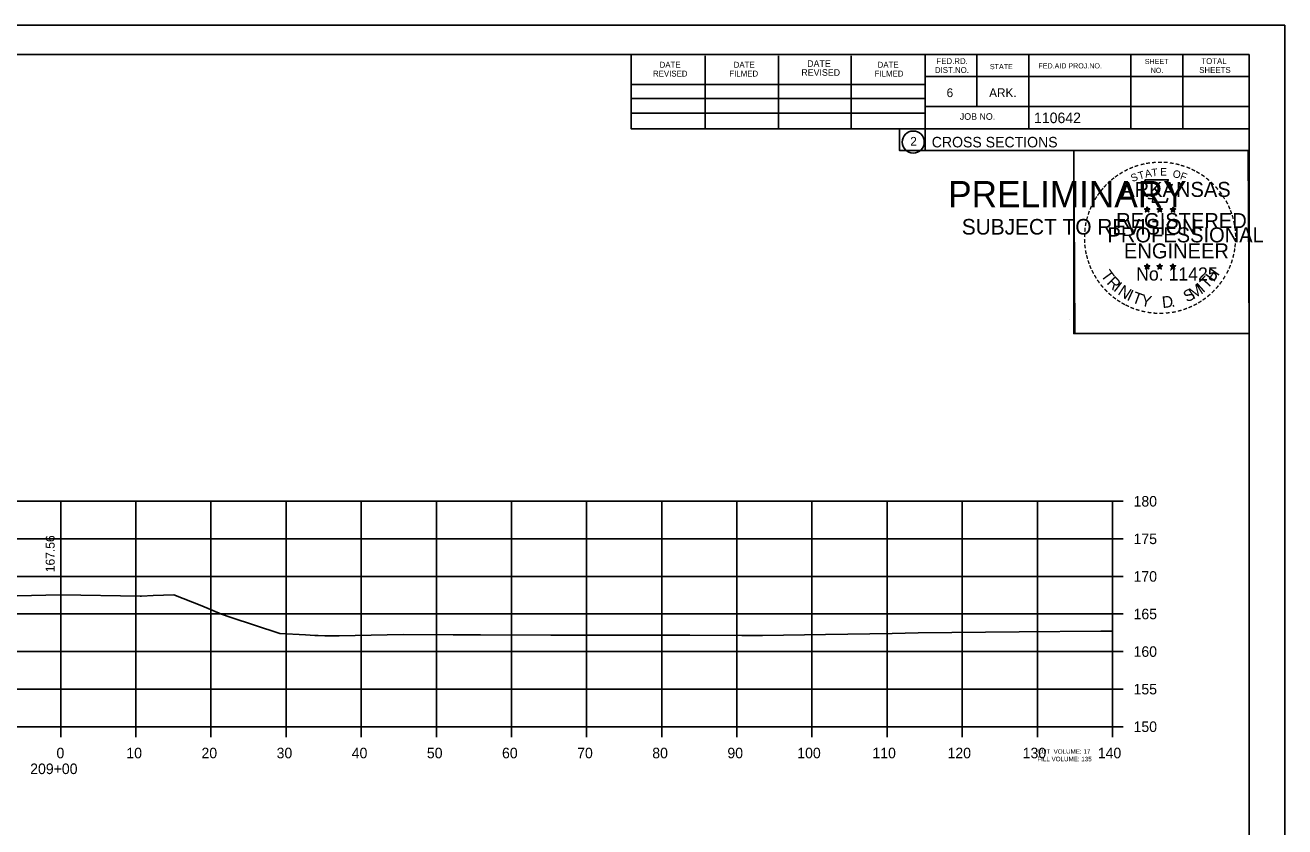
# Model space of a CAD drawing. Extents: x 1368503 to 1373085, y 379840 to 381833.
# Drawn here: x 1368668.3 to 1368836, y 380446.1 to 380552.7 of the extents above; entities that cross this region are included whole.
import ezdxf

# ---------------------------------------------------------------- set-up
doc = ezdxf.new("R2010")
doc.units = 0
for name, color, linetype in [('S_BRIDGE', 7, 'Continuous'), ('S_EDGE_PAVEMENT', 7, 'Continuous'), ('S_LANDSCAPING', 7, 'Continuous'), ('S_MISC_BOUNDARY', 7, 'Continuous'), ('S_MISC_BOUNDARY_ANNOT', 7, 'Continuous'), ('S_PHOTO_CENTERS', 7, 'Continuous'), ('S_PHOTO_NOTES', 7, 'Continuous'), ('S_TRAILS', 7, 'Continuous'), ('S_TRAILS_ANNOT', 7, 'Continuous')]:
    doc.layers.add(name, color=color, linetype=linetype)

msp = doc.modelspace()

# ---------------------------------------------------------------- linework, layer by layer
at = {"layer": 'S_BRIDGE'}
for p, q in [((1368515.06, 380548.83), (1368831.24, 380548.83)), ((1368748.98, 380538.95), (1368748.98, 380548.83)), ((1368758.84, 380538.95), (1368758.84, 380548.63)), ((1368768.6, 380538.95), (1368768.6, 380548.63)), ((1368778.28, 380538.95), (1368778.28, 380548.63)), ((1368788.14, 380548.83), (1368788.14, 380536.03)), ((1368794.98, 380548.83), (1368794.98, 380541.89)), ((1368801.92, 380548.83), (1368801.92, 380538.95)), ((1368815.5, 380548.83), (1368815.5, 380538.95)), ((1368822.44, 380548.83), (1368822.44, 380538.95)), ((1368831.24, 380343.37), (1368831.24, 380548.83)), ((1368831.24, 380545.89), (1368788.14, 380545.89)), ((1368831.24, 380545.91), (1368831.24, 380545.91)), ((1368748.98, 380544.81), (1368788.14, 380544.81)), ((1368748.98, 380542.95), (1368788.14, 380542.95)), ((1368748.98, 380538.95), (1368748.98, 380541.01)), ((1368748.98, 380541.01), (1368788.14, 380541.01)), ((1368831.24, 380541.89), (1368788.14, 380541.89)), ((1368791.1, 380541.89), (1368831.24, 380541.89)), ((1368831.24, 380538.95), (1368748.98, 380538.95)), ((1368788.14, 380536.03), (1368831.24, 380536.03))]:
    msp.add_line(p, q, dxfattribs=at)
msp.add_circle((1368786.53, 380537.16), 1.47, dxfattribs=at)
at = {"layer": 'S_EDGE_PAVEMENT'}
for p, q in [((1368813.06, 380459.37), (1368813.06, 380489.37)), ((1368814.46, 380489.37), (1368813.06, 380489.37)), ((1368814.46, 380484.37), (1368813.06, 380484.37)), ((1368814.46, 380479.37), (1368813.06, 380479.37)), ((1368814.46, 380474.37), (1368813.06, 380474.37)), ((1368814.46, 380469.37), (1368813.06, 380469.37)), ((1368814.46, 380464.37), (1368813.06, 380464.37)), ((1368533.06, 380459.37), (1368813.06, 380459.37)), ((1368673.06, 380457.97), (1368673.06, 380459.37)), ((1368683.06, 380457.97), (1368683.06, 380459.37)), ((1368693.06, 380457.97), (1368693.06, 380459.37)), ((1368703.06, 380457.97), (1368703.06, 380459.37)), ((1368713.06, 380457.97), (1368713.06, 380459.37)), ((1368723.06, 380457.97), (1368723.06, 380459.37)), ((1368733.06, 380457.97), (1368733.06, 380459.37)), ((1368743.06, 380457.97), (1368743.06, 380459.37)), ((1368753.06, 380457.97), (1368753.06, 380459.37)), ((1368763.06, 380457.97), (1368763.06, 380459.37)), ((1368773.06, 380457.97), (1368773.06, 380459.37)), ((1368783.06, 380457.97), (1368783.06, 380459.37)), ((1368793.06, 380457.97), (1368793.06, 380459.37)), ((1368803.06, 380457.97), (1368803.06, 380459.37)), ((1368813.06, 380457.97), (1368813.06, 380459.37)), ((1368814.46, 380459.37), (1368813.06, 380459.37))]:
    msp.add_line(p, q, dxfattribs=at)
at = {"layer": 'S_LANDSCAPING'}
for p, q in [((1368817.32, 380528.28), (1368817.67, 380528.17)), ((1368817.32, 380528.28), (1368817.58, 380528.24)), ((1368817.32, 380528.28), (1368817.56, 380528.16)), ((1368817.46, 380527.87), (1368817.67, 380528.17)), ((1368817.46, 380527.87), (1368817.58, 380528.12)), ((1368817.46, 380527.87), (1368817.67, 380528.09)), ((1368817.67, 380528.54), (1368817.63, 380528.28)), ((1368817.67, 380528.17), (1368817.67, 380528.54)), ((1368817.67, 380528.54), (1368817.72, 380528.29)), ((1368818.02, 380528.28), (1368817.67, 380528.17)), ((1368817.89, 380527.87), (1368817.67, 380528.17)), ((1368817.89, 380527.87), (1368817.67, 380528.09)), ((1368818.02, 380528.28), (1368817.73, 380528.23)), ((1368817.89, 380527.87), (1368817.75, 380528.16)), ((1368818.02, 380528.28), (1368817.82, 380528.18)), ((1368818.99, 380528.28), (1368819.34, 380528.17)), ((1368818.99, 380528.28), (1368819.25, 380528.24)), ((1368818.99, 380528.28), (1368819.23, 380528.16)), ((1368819.13, 380527.87), (1368819.34, 380528.17)), ((1368819.13, 380527.87), (1368819.25, 380528.12)), ((1368819.13, 380527.87), (1368819.34, 380528.09)), ((1368819.34, 380528.54), (1368819.3, 380528.28)), ((1368819.34, 380528.17), (1368819.34, 380528.54)), ((1368819.34, 380528.54), (1368819.39, 380528.29)), ((1368819.69, 380528.28), (1368819.34, 380528.17)), ((1368819.56, 380527.87), (1368819.34, 380528.17)), ((1368819.56, 380527.87), (1368819.34, 380528.09)), ((1368819.69, 380528.28), (1368819.4, 380528.23)), ((1368819.56, 380527.87), (1368819.42, 380528.16)), ((1368819.69, 380528.28), (1368819.49, 380528.18)), ((1368820.76, 380528.27), (1368821.11, 380528.16)), ((1368820.76, 380528.27), (1368821.01, 380528.22)), ((1368820.76, 380528.27), (1368820.99, 380528.15)), ((1368820.89, 380527.86), (1368821.11, 380528.16)), ((1368820.89, 380527.86), (1368821.02, 380528.11)), ((1368820.89, 380527.86), (1368821.1, 380528.08)), ((1368821.11, 380528.52), (1368821.07, 380528.27)), ((1368821.32, 380527.86), (1368821.1, 380528.08)), ((1368821.11, 380528.16), (1368821.11, 380528.52)), ((1368821.11, 380528.52), (1368821.16, 380528.27)), ((1368821.45, 380528.27), (1368821.11, 380528.16)), ((1368821.32, 380527.86), (1368821.11, 380528.16)), ((1368821.45, 380528.27), (1368821.17, 380528.22)), ((1368821.32, 380527.86), (1368821.18, 380528.15)), ((1368821.45, 380528.27), (1368821.25, 380528.17)), ((1368817.32, 380520.71), (1368817.67, 380520.6)), ((1368817.32, 380520.71), (1368817.57, 380520.66)), ((1368817.32, 380520.71), (1368817.56, 380520.59)), ((1368817.67, 380520.96), (1368817.63, 380520.71)), ((1368817.67, 380520.6), (1368817.67, 380520.96)), ((1368817.67, 380520.96), (1368817.72, 380520.71)), ((1368818.02, 380520.71), (1368817.67, 380520.6)), ((1368818.02, 380520.71), (1368817.73, 380520.66)), ((1368818.02, 380520.71), (1368817.81, 380520.61)), ((1368818.99, 380520.71), (1368819.34, 380520.6)), ((1368818.99, 380520.71), (1368819.24, 380520.66)), ((1368818.99, 380520.71), (1368819.23, 380520.59)), ((1368819.34, 380520.96), (1368819.3, 380520.71)), ((1368819.34, 380520.6), (1368819.34, 380520.96)), ((1368819.34, 380520.96), (1368819.39, 380520.71)), ((1368819.68, 380520.71), (1368819.34, 380520.6)), ((1368819.68, 380520.71), (1368819.4, 380520.66)), ((1368819.68, 380520.71), (1368819.48, 380520.61)), ((1368820.76, 380520.7), (1368821.1, 380520.59)), ((1368820.76, 380520.7), (1368821.01, 380520.65)), ((1368820.76, 380520.7), (1368820.99, 380520.58)), ((1368821.1, 380520.95), (1368821.06, 380520.7)), ((1368821.1, 380520.59), (1368821.1, 380520.95)), ((1368821.1, 380520.95), (1368821.15, 380520.7)), ((1368821.45, 380520.7), (1368821.1, 380520.59)), ((1368821.45, 380520.7), (1368821.17, 380520.65)), ((1368821.45, 380520.7), (1368821.25, 380520.6)), ((1368817.45, 380520.3), (1368817.67, 380520.6)), ((1368817.45, 380520.3), (1368817.58, 380520.54)), ((1368817.45, 380520.3), (1368817.67, 380520.52)), ((1368817.88, 380520.3), (1368817.67, 380520.6)), ((1368817.88, 380520.3), (1368817.67, 380520.51)), ((1368817.88, 380520.3), (1368817.74, 380520.59)), ((1368819.12, 380520.3), (1368819.34, 380520.6)), ((1368819.12, 380520.3), (1368819.25, 380520.54)), ((1368819.12, 380520.3), (1368819.34, 380520.52)), ((1368819.55, 380520.3), (1368819.34, 380520.6)), ((1368819.55, 380520.3), (1368819.34, 380520.51)), ((1368819.55, 380520.3), (1368819.41, 380520.59)), ((1368820.89, 380520.29), (1368821.1, 380520.59)), ((1368820.89, 380520.29), (1368821.01, 380520.53)), ((1368820.89, 380520.29), (1368821.1, 380520.51)), ((1368821.32, 380520.29), (1368821.1, 380520.59)), ((1368821.32, 380520.29), (1368821.1, 380520.5)), ((1368821.32, 380520.29), (1368821.18, 380520.58))]:
    msp.add_line(p, q, dxfattribs=at)
for points in [[(1368817.36, 380532.16), (1368817.63, 380531.33)], [(1368820.88, 380531.24), (1368821.02, 380531.52), (1368820.33, 380531.5), (1368820.48, 380532.16), (1368817.36, 380532.16)], [(1368817.86, 380529.74), (1368817.86, 380529.65), (1368818.42, 380529.63), (1368818.37, 380529.16), (1368820.24, 380529.16), (1368820.44, 380529.69)], [(1368817.67, 380528.54), (1368817.89, 380527.87), (1368817.32, 380528.28), (1368818.02, 380528.28), (1368817.46, 380527.87), (1368817.67, 380528.54)], [(1368819.34, 380528.54), (1368819.56, 380527.87), (1368818.99, 380528.28), (1368819.69, 380528.28), (1368819.13, 380527.87), (1368819.34, 380528.54)], [(1368821.11, 380528.52), (1368821.32, 380527.86), (1368820.76, 380528.27), (1368821.45, 380528.27), (1368820.89, 380527.86), (1368821.11, 380528.52)], [(1368817.67, 380520.96), (1368817.88, 380520.3), (1368817.32, 380520.71), (1368818.02, 380520.71), (1368817.45, 380520.3), (1368817.67, 380520.96)], [(1368819.34, 380520.96), (1368819.55, 380520.3), (1368818.99, 380520.71), (1368819.68, 380520.71), (1368819.12, 380520.3), (1368819.34, 380520.96)], [(1368821.1, 380520.95), (1368821.32, 380520.29), (1368820.76, 380520.7), (1368821.45, 380520.7), (1368820.89, 380520.29), (1368821.1, 380520.95)]]:
    msp.add_lwpolyline(points, dxfattribs=at)
for centre, radius in [((1368817.67, 380528.17), 0.172), ((1368817.67, 380528.17), 0.145), ((1368817.67, 380528.17), 0.116), ((1368817.67, 380528.17), 0.0991), ((1368817.67, 380528.17), 0.0747), ((1368817.67, 380528.17), 0.0495), ((1368817.67, 380528.17), 0.0296), ((1368819.34, 380528.17), 0.172), ((1368819.34, 380528.17), 0.145), ((1368819.34, 380528.17), 0.116), ((1368819.34, 380528.17), 0.0991), ((1368819.34, 380528.17), 0.0747), ((1368819.34, 380528.17), 0.0495), ((1368819.34, 380528.17), 0.0296), ((1368821.11, 380528.16), 0.172), ((1368821.11, 380528.16), 0.145), ((1368821.11, 380528.16), 0.116), ((1368821.11, 380528.16), 0.0991), ((1368821.11, 380528.16), 0.0747), ((1368821.11, 380528.16), 0.0495), ((1368821.11, 380528.16), 0.0296), ((1368817.67, 380520.6), 0.172), ((1368817.67, 380520.6), 0.145), ((1368817.67, 380520.6), 0.116), ((1368817.67, 380520.6), 0.0991), ((1368819.34, 380520.6), 0.172), ((1368819.34, 380520.6), 0.145), ((1368819.34, 380520.6), 0.116), ((1368819.34, 380520.6), 0.0991), ((1368821.1, 380520.59), 0.172), ((1368821.1, 380520.59), 0.145), ((1368821.1, 380520.59), 0.116), ((1368817.67, 380520.6), 0.0747), ((1368817.67, 380520.6), 0.0495), ((1368817.67, 380520.6), 0.0296), ((1368819.34, 380520.6), 0.0747), ((1368819.34, 380520.6), 0.0495), ((1368819.34, 380520.6), 0.0296), ((1368821.1, 380520.59), 0.0991), ((1368821.1, 380520.59), 0.0747), ((1368821.1, 380520.59), 0.0495), ((1368821.1, 380520.59), 0.0296)]:
    msp.add_circle(centre, radius, dxfattribs=at)
at = {"layer": 'S_MISC_BOUNDARY'}
msp.add_lwpolyline([(1368663.39, 380476.72), (1368673, 380476.93), (1368673.07, 380476.93), (1368673.14, 380476.93), (1368683.64, 380476.73), (1368683.8, 380476.73), (1368685.36, 380476.81), (1368688.14, 380476.94), (1368691.83, 380475.44), (1368694.46, 380474.36), (1368695.63, 380473.97), (1368702.24, 380471.79), (1368705.64, 380471.59), (1368706.88, 380471.52), (1368707.31, 380471.5), (1368708.2, 380471.46), (1368710.12, 380471.48), (1368718.64, 380471.64), (1368725.31, 380471.59), (1368728.94, 380471.58), (1368738.31, 380471.57), (1368756.79, 380471.55), (1368763.73, 380471.52), (1368766.47, 380471.5), (1368774.85, 380471.65), (1368783.71, 380471.79), (1368787.18, 380471.85), (1368800.62, 380471.98), (1368811.49, 380472.08), (1368813.06, 380472.1)], dxfattribs=at)
at = {"layer": 'S_PHOTO_CENTERS'}
for p, q in [((1368533.06, 380489.37), (1368813.06, 380489.37)), ((1368673.06, 380459.37), (1368673.06, 380489.37)), ((1368683.06, 380459.37), (1368683.06, 380489.37)), ((1368693.06, 380459.37), (1368693.06, 380489.37)), ((1368703.06, 380459.37), (1368703.06, 380489.37)), ((1368713.06, 380459.37), (1368713.06, 380489.37)), ((1368723.06, 380459.37), (1368723.06, 380489.37)), ((1368733.06, 380459.37), (1368733.06, 380489.37)), ((1368743.06, 380459.37), (1368743.06, 380489.37)), ((1368753.06, 380459.37), (1368753.06, 380489.37)), ((1368763.06, 380459.37), (1368763.06, 380489.37)), ((1368773.06, 380459.37), (1368773.06, 380489.37)), ((1368783.06, 380459.37), (1368783.06, 380489.37)), ((1368793.06, 380459.37), (1368793.06, 380489.37)), ((1368803.06, 380459.37), (1368803.06, 380489.37)), ((1368813.06, 380459.37), (1368813.06, 380489.37)), ((1368533.06, 380484.37), (1368813.06, 380484.37)), ((1368533.06, 380479.37), (1368813.06, 380479.37)), ((1368533.06, 380474.37), (1368813.06, 380474.37)), ((1368533.06, 380469.37), (1368813.06, 380469.37)), ((1368533.06, 380464.37), (1368813.06, 380464.37)), ((1368533.06, 380459.37), (1368813.06, 380459.37))]:
    msp.add_line(p, q, dxfattribs=at)
at = {"layer": 'S_PHOTO_NOTES'}
for p, q in [((1368502.66, 380552.72), (1368835.99, 380552.72)), ((1368807.27, 380513.57), (1368807.27, 380513.57))]:
    msp.add_line(p, q, dxfattribs=at)
for points in [[(1368502.65, 380552.72), (1368835.99, 380552.72), (1368835.99, 380339.38), (1368502.65, 380339.38)], [(1368748.98, 380548.83), (1368748.98, 380538.95), (1368784.71, 380538.95), (1368784.71, 380536.03), (1368807.91, 380536.03), (1368807.91, 380511.69), (1368831.24, 380511.69), (1368831.24, 380343.37), (1368515.06, 380343.37), (1368515.06, 380548.83)], [(1368807.91, 380536.03), (1368831.12, 380536.03), (1368831.24, 380511.69), (1368808.03, 380511.69)]]:
    msp.add_lwpolyline(points, close=True, dxfattribs=at)

# ---------------------------------------------------------------- texts
at = {"layer": 'S_BRIDGE'}
for s, height, p in [('DATE', 0.782, (1368752.78, 380547.07)), ('DATE', 0.782, (1368762.64, 380547.07)), ('DATE', 0.879, (1368772.42, 380547.17)), ('DATE', 0.782, (1368781.8, 380547.07)), ('FED.RD.', 0.782, (1368789.62, 380547.55)), ('STATE', 0.684, (1368796.74, 380546.87)), ('FED.AID PROJ.NO.', 0.684, (1368803.2, 380546.97)), ('SHEET', 0.684, (1368817.36, 380547.55)), ('TOTAL', 0.782, (1368824.88, 380547.55)), ('REVISED', 0.782, (1368751.9, 380545.89)), ('FILMED', 0.782, (1368762.06, 380545.89)), ('REVISED', 0.879, (1368771.64, 380545.99)), ('FILMED', 0.782, (1368781.4, 380545.89)), ('DIST.NO.', 0.782, (1368789.42, 380546.37)), ('NO.', 0.684, (1368818.14, 380546.37)), ('SHEETS', 0.782, (1368824.6, 380546.37)), ('6', 1.17, (1368790.98, 380543.15)), ('ARK.', 1.172, (1368796.64, 380543.15)), ('JOB NO.', 0.879, (1368792.74, 380540.13)), ('110642', 1.4, (1368802.61, 380539.69)), ('2', 1.17, (1368786.14, 380536.68)), ('CROSS SECTIONS', 1.4, (1368789, 380536.46))]:
    msp.add_text(s, height=height, rotation=360, dxfattribs=at).set_placement(p)
at = {"layer": 'S_LANDSCAPING'}
for s, height, rotation, p in [('-', 1.6, 19.1761, (1368816.11, 380533.29)), ('-', 1.6, 13.6301, (1368816.86, 380533.53)), ('-', 1.6, 10.2193, (1368817.54, 380533.69)), ('-', 1.6, 5.8968, (1368818.27, 380533.8)), ('-', 1.6, 0.1862, (1368819.04, 380533.87)), ('-', 1.6, 357.743, (1368819.76, 380533.86)), ('-', 1.6, 352.1617, (1368820.51, 380533.8)), ('-', 1.6, 347.2049, (1368821.23, 380533.69)), ('-', 1.6, 342.3362, (1368821.86, 380533.53)), ('-', 1.6, 38.9507, (1368813.19, 380531.56)), ('-', 1.6, 36.2317, (1368813.67, 380531.94)), ('-', 1.6, 34.0636, (1368814.25, 380532.33)), ('-', 1.6, 28.7918, (1368814.85, 380532.7)), ('-', 1.6, 24.3072, (1368815.48, 380533.02)), ('S', 1, 21.594, (1368815.72, 380531.84)), ('T', 1, 16.4036, (1368816.63, 380532.17)), ('A', 1, 11.2132, (1368817.46, 380532.42)), ('T', 1, 6.0228, (1368818.31, 380532.59)), ('E', 1, 0.8323, (1368819.41, 380532.7)), ('O', 1, 350.4515, (1368821.02, 380532.49)), ('F', 1, 340.0707, (1368821.97, 380532.26)), ('-', 1.6, 337.8551, (1368822.6, 380533.31)), ('-', 1.6, 334.1211, (1368823.23, 380533.04)), ('-', 1.6, 329.6409, (1368823.81, 380532.76)), ('-', 1.6, 325.8627, (1368824.45, 380532.4)), ('-', 1.6, 320.5297, (1368825.06, 380531.97)), ('-', 1.6, 50.6142, (1368811.91, 380530.18)), ('-', 1.6, 48.423, (1368812.31, 380530.66)), ('-', 1.6, 42.9622, (1368812.76, 380531.14)), ('ARKANSAS', 2, 360, (1368814.22, 380529.87)), ('-', 1.6, 315.5786, (1368825.66, 380531.48)), ('-', 1.6, 309.8797, (1368826.23, 380530.93)), ('-', 1.6, 62.8713, (1368810.86, 380528.47)), ('-', 1.6, 58.0706, (1368811.17, 380529.08)), ('-', 1.6, 54.2325, (1368811.5, 380529.61)), ('-', 1.6, 306.6522, (1368826.75, 380530.33)), ('-', 1.4, 303.6753, (1368827.24, 380529.76)), ('-', 1.6, 299.6684, (1368827.56, 380529.15)), ('-', 1.6, 72.3945, (1368810.38, 380527.23)), ('-', 1.6, 67.7743, (1368810.6, 380527.86)), ('REGISTERED', 2, 360, (1368813.54, 380525.72)), ('DWB', 0.01, 360, (1368817.66, 380528.16)), ('DWB', 0.01, 360, (1368819.33, 380528.16)), ('DWB', 0.01, 360, (1368821.09, 380528.15)), ('-', 1.6, 294.6628, (1368827.88, 380528.54)), ('-', 1.6, 290.5728, (1368828.14, 380527.97)), ('-', 1.6, 285.1233, (1368828.37, 380527.39)), ('-', 1.6, 85.1863, (1368809.98, 380525.11)), ('-', 1.6, 81.2013, (1368810.05, 380525.8)), ('-', 1.6, 75.461, (1368810.18, 380526.51)), ('PROFESSIONAL', 2, 360, (1368812.39, 380523.82)), ('-', 1.6, 280.5493, (1368828.57, 380526.64)), ('-', 1.6, 276.5962, (1368828.74, 380525.88)), ('-', 1.6, 94.1959, (1368809.99, 380523.68)), ('-', 1.6, 89.0622, (1368809.95, 380524.41)), ('-', 1.6, 274.3301, (1368828.8, 380525.15)), ('-', 1.6, 269.9407, (1368828.83, 380524.52)), ('-', 1.6, 98.9479, (1368810.06, 380523.02)), ('-', 1.6, 101.7149, (1368810.19, 380522.28)), ('ENGINEER', 2, 360, (1368814.58, 380521.69)), ('-', 1.6, 260.9953, (1368828.74, 380523.2)), ('-', 1.6, 263.5172, (1368828.81, 380523.86)), ('-', 1.6, 105.4578, (1368810.36, 380521.69)), ('-', 1.6, 109.0874, (1368810.57, 380521.06)), ('-', 1.6, 114.0643, (1368810.82, 380520.46)), ('-', 1.6, 247.8887, (1368828.23, 380521.13)), ('-', 1.6, 252.8681, (1368828.45, 380521.8)), ('-', 1.6, 255.7626, (1368828.63, 380522.52)), ('-', 1.6, 115.7289, (1368811.13, 380519.84)), ('-', 1.6, 120.4471, (1368811.49, 380519.26)), ('T', 1.54, 306.0406, (1368811.43, 380519.44)), ('R', 1.54, 314.005, (1368812.19, 380518.39)), ('No. 11425', 1.757, 360, (1368816.21, 380518.74)), ('DWB', 0.01, 360, (1368817.66, 380520.59)), ('DWB', 0.01, 360, (1368819.33, 380520.59)), ('DWB', 0.01, 360, (1368821.09, 380520.58)), ('T', 1.54, 46.6444, (1368825.66, 380517.53)), ('H', 1.54, 54.6088, (1368826.55, 380518.47)), ('-', 1.6, 239.0712, (1368827.57, 380519.75)), ('-', 1.6, 244.6197, (1368827.96, 380520.5)), ('-', 1.6, 125.8934, (1368811.89, 380518.7)), ('-', 1.6, 130.7181, (1368812.35, 380518.14)), ('-', 1.6, 134.2238, (1368812.87, 380517.6)), ('I', 1.54, 321.9694, (1368813.09, 380517.46)), ('N', 1.54, 326.5002, (1368813.66, 380516.98)), ('I', 1.54, 335.3603, (1368814.87, 380516.2)), ('S', 1.54, 26.9312, (1368822.97, 380515.8)), ('M', 1.54, 32.6563, (1368823.81, 380516.2)), ('I', 1.54, 42.1136, (1368825.1, 380517.05)), ('-', 1.6, 225.7653, (1368826.26, 380517.97)), ('-', 1.6, 231.2538, (1368826.74, 380518.53)), ('-', 1.6, 233.8452, (1368827.17, 380519.1)), ('-', 1.6, 138.9338, (1368813.39, 380517.14)), ('-', 1.6, 144.6463, (1368813.95, 380516.73)), ('-', 1.6, 148.0898, (1368814.51, 380516.36)), ('-', 1.6, 151.5704, (1368815.09, 380516.03)), ('T', 1.54, 339.8912, (1368815.53, 380515.87)), ('Y', 1.54, 347.8556, (1368816.74, 380515.43)), ('D', 1.54, 6.3969, (1368819.73, 380515.07)), ('-', 1.6, 207.3568, (1368824.1, 380516.25)), ('-', 1.6, 212.2491, (1368824.65, 380516.6)), ('-', 1.6, 215.7363, (1368825.19, 380516.99)), ('-', 1.6, 221.0851, (1368825.74, 380517.46)), ('-', 1.6, 154.6002, (1368815.61, 380515.79)), ('-', 1.6, 158.5612, (1368816.24, 380515.53)), ('-', 1.6, 162.7983, (1368816.92, 380515.32)), ('-', 1.6, 167.5555, (1368817.64, 380515.16)), ('-', 1.6, 173.1155, (1368818.41, 380515.05)), ('-', 1.6, 176.5183, (1368819.16, 380514.99)), ('-', 1.6, 181.5918, (1368819.9, 380515.01)), ('-', 1.6, 185.8167, (1368820.71, 380515.09)), ('-', 1.6, 191.2858, (1368821.45, 380515.22)), ('.', 1.54, 13.7642, (1368820.92, 380515.19)), ('-', 1.6, 195.4743, (1368822.18, 380515.42)), ('-', 1.6, 200.7184, (1368822.85, 380515.66)), ('-', 1.6, 204.2516, (1368823.47, 380515.93))]:
    msp.add_text(s, height=height, rotation=rotation, dxfattribs=at).set_placement(p)
at = {"layer": 'S_MISC_BOUNDARY_ANNOT'}
for s, height, p in [('PRELIMINARY', 3.5, (1368791.19, 380528.49)), ('DWB', 0.01, (1368791.94, 380530.34)), ('SUBJECT TO REVISION', 2.0751, (1368793, 380524.86))]:
    msp.add_text(s, height=height, rotation=360, dxfattribs=at).set_placement(p)
at = {"layer": 'S_TRAILS'}
for s, height, p in [('180', 1.4, (1368815.86, 380488.67)), ('175', 1.4, (1368815.86, 380483.67)), ('170', 1.4, (1368815.86, 380478.67)), ('165', 1.4, (1368815.86, 380473.67)), ('160', 1.4, (1368815.86, 380468.67)), ('155', 1.4, (1368815.86, 380463.67)), ('150', 1.4, (1368815.86, 380458.67)), ('0', 1.4, (1368672.5, 380455.17)), ('10', 1.4, (1368681.8, 380455.17)), ('20', 1.4, (1368691.8, 380455.17)), ('30', 1.4, (1368701.8, 380455.17)), ('40', 1.4, (1368711.8, 380455.17)), ('50', 1.4, (1368721.8, 380455.17)), ('60', 1.4, (1368731.8, 380455.17)), ('70', 1.4, (1368741.8, 380455.17)), ('80', 1.4, (1368751.8, 380455.17)), ('90', 1.4, (1368761.8, 380455.17)), ('100', 1.4, (1368771.1, 380455.17)), ('110', 1.4, (1368781.1, 380455.17)), ('120', 1.4, (1368791.1, 380455.17)), ('130', 1.4, (1368801.1, 380455.17)), ('CUT  VOLUME: 17', 0.6, (1368803.06, 380455.77)), ('FILL VOLUME: 135', 0.6, (1368803.06, 380454.77)), ('140', 1.4, (1368811.1, 380455.17)), ('209+00', 1.4, (1368669, 380453.07))]:
    msp.add_text(s, height=height, dxfattribs=at).set_placement(p)
at = {"layer": 'S_TRAILS_ANNOT'}
msp.add_text('167.56', height=1.2, rotation=90, dxfattribs=at).set_placement((1368672.26, 380479.93))

doc.saveas('drawing.dxf')
